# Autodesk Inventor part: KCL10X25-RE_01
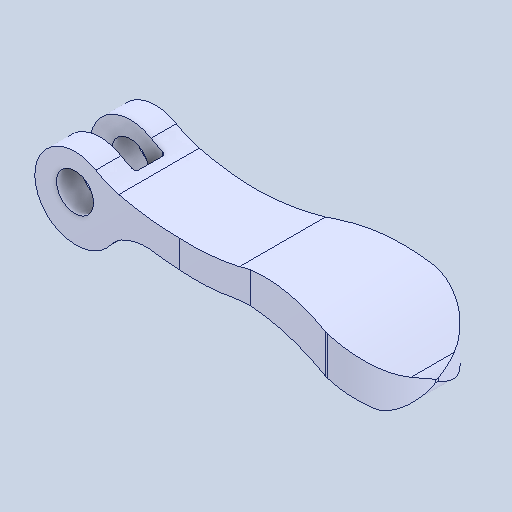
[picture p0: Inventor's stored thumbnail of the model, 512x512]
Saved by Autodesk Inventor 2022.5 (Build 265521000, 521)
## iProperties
Created: 2024-08
Part Number: KCL10X25-RE_01
Material: 一般
Document SubType Name: Modeling
Designer: ImaoCorp
Density: 1 g/cm^3
Appearance: 既定
Author: ImaoCorp
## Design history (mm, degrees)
feature "KCL10X25-RE_01"
node "ソリッド1"
